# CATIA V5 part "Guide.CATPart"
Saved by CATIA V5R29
Part number: Guide_02
Source: Unknown
Bounding box of the stored display mesh (mm): x -40 to 20, y -40 to 40, z -1100 to 991.193
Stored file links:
  C:\가치같이\SmartFactory_BoxErectorConveyor\Guide.CATPart
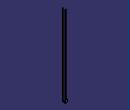
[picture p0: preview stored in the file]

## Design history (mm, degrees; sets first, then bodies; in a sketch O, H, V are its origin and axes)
Body1 (main body)
  Solid1 "PartBody": solid without history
